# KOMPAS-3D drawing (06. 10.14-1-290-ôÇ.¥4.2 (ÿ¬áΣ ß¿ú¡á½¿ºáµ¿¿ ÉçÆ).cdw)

Views: Вид 1
Referenced files: клемный ряд.cdw
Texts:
  Текст на чертеже
  Размерные надписи
  Шероховатость
  Линия-выноска #1
  Линия-выноска #2
  Линия-выноска #3
  Отклонения формы и база
  Заголовок таблицы
  Ячейка таблицы
  Стрелка вида
  Обозначение изменения
  Фигурная скобка
  Номер узла
  Марка координационной оси
  VRCB
  Выносная надпись
  Обозначение узла
  Марка/позиционное обозначение с линией-выноской
  Марка/позиционное обозначение на линии
  Марка/позиционное обозначение без линии-выноски
  Условно-графические обозначения:
  Цепи переменного тока
  Правая боковина
  Ряды зажимов
  Левая боковина
  Цепи оперативного тока
  Колодка маркировочная
  Клемма измерительная
  Торцевая крышка
  Клемма проходная
  Н.контр
  Шкаф сигнализации РЗТ.
  Схема рядов зажимов.
  Борисов
  Разраб.
  Реконструкция ПС 110 кВ Опорная
  (замена трансформаторов 16МВА на 40МВА)
Dimensions and other numbers on the sheet: 10/14-1-290-УА.Э4.2; 7; 02; 5; 6; 4; 3; 2; 1; 8; 9; 10; 11; 12; 13; 14; 01; 30; 28; 29; 17; 18; 19; 20; 21; 22; 23; 24; 25; 26; 27; 16; 15; 86/02-19-01-290-УА.Э4.2-; 11.12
